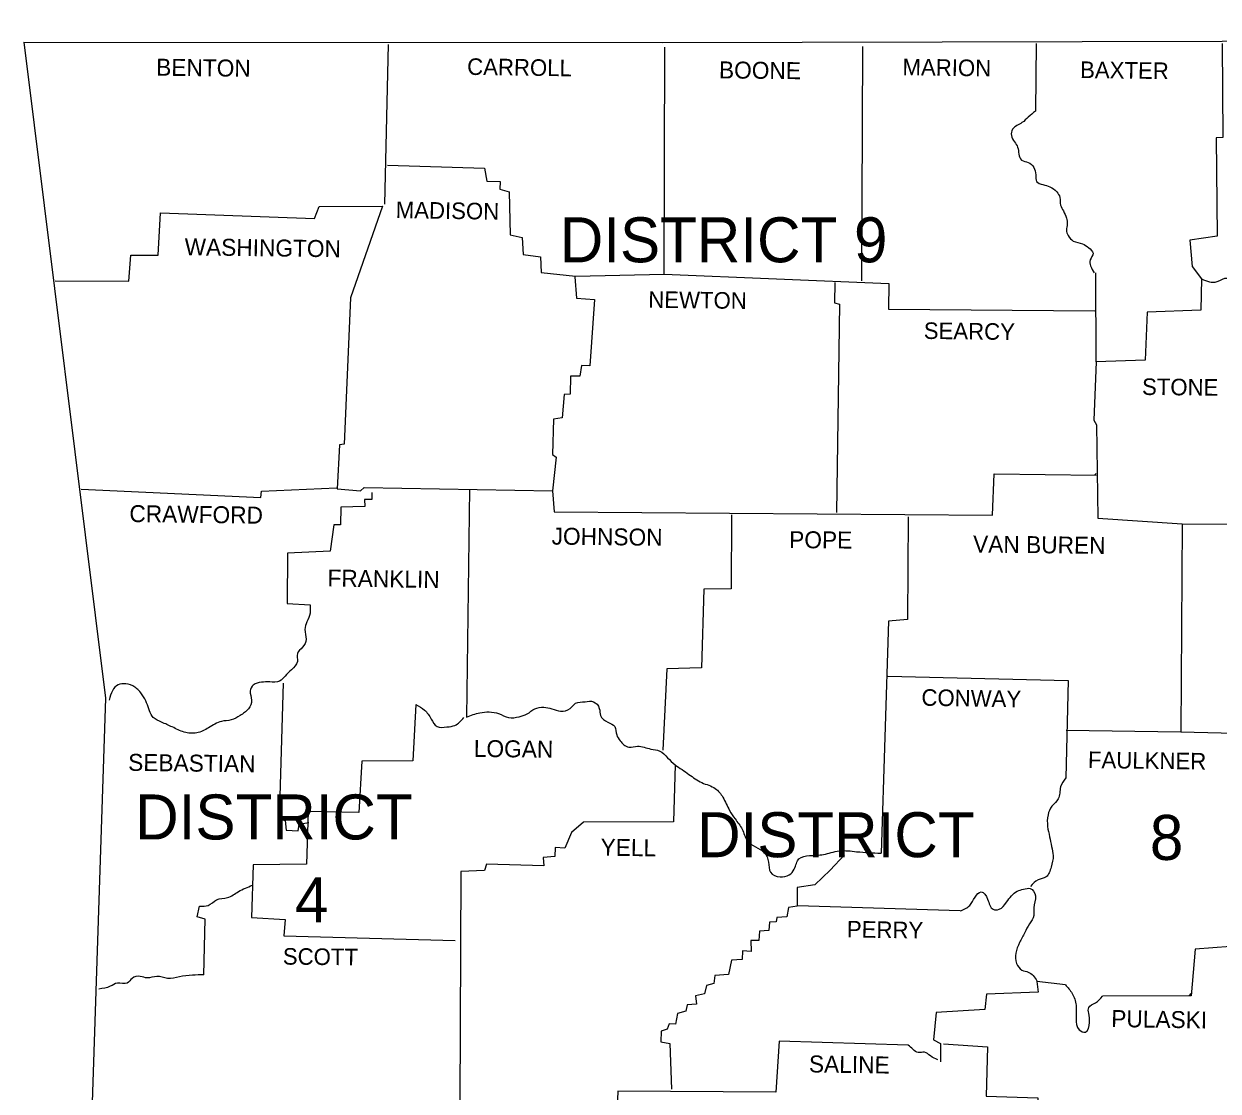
# Model space of a CAD drawing. Extents: x -42408 to 34530, y -43140 to 20491.
# Drawn here: x 1592 to 3107, y -8503 to -7149 of the extents above; entities that cross this region are included whole.
import ezdxf

# ---------------------------------------------------------------- set-up
doc = ezdxf.new("R2010")
doc.units = 0
for name, color, linetype in [('1', 7, 'Continuous'), ('2', 7, 'Continuous'), ('3', 7, 'Continuous')]:
    doc.layers.add(name, color=color, linetype=linetype)

msp = doc.modelspace()

# ---------------------------------------------------------------- linework, layer by layer
at = {"layer": '1'}
for points in [[(1592.1, -7172.4), (2401.7, -7172.9), (3112.1, -7171.4), (3950.2, -7158.4), (4338.7, -7149.4)], [(1592.1, -7172.4), (1695.7, -8004.5), (1650.7, -9362.9)], [(2054.2, -7175.4), (2049.7, -7378.2)], [(2053.2, -7328.6), (2176.4, -7332.6), (2179.4, -7348.7), (2196.4, -7349.2), (2195.9, -7359.2), (2207.9, -7362.2), (2208.9, -7416.8), (2224.4, -7420.3), (2225.4, -7441.8), (2247.5, -7444.8), (2248.5, -7464.8), (2292, -7469.3), (2404.2, -7466.8), (2405.2, -7178.9)], [(2656, -7177.9), (2654.5, -7475.3)], [(2876.3, -7174.4), (2875.3, -7260.1)], [(3112.1, -7174.4), (3113.1, -7293.6), (3104.6, -7294.1), (3106.1, -7418.8), (3071.1, -7423.8), (3074.1, -7457.3), (3086.1, -7472.8), (3085.1, -7512.4), (3017, -7514.9), (3014.5, -7576), (2952.4, -7578), (2949.4, -7652.1), (2952.9, -7658.1), (2954.4, -7776.2), (3061.5, -7783.3), (3060, -8047.1), (3145.2, -8049.6), (3145.2, -8318), (3078.1, -8323), (3073.1, -8382), (2960.4, -8382.6)], [(1631.6, -7475.3), (1725.3, -7475.8), (1727.8, -7442.8), (1762.3, -7442.8), (1765.3, -7389.2), (1960.6, -7396.2), (1966.6, -7381.2), (2047.2, -7380.7), (2006.6, -7496.9), (1998.6, -7682.6), (1992.6, -7683.1), (1989.6, -7739.2), (2019.1, -7741.7), (2023.7, -7737.2), (2262.5, -7741.7), (2265, -7768.2)], [(2404.2, -7466.8), (2689.5, -7478.8), (2689, -7511.4), (2950.9, -7513.4)], [(2952.4, -7578), (2951.9, -7465.3)], [(2291, -7470.3), (2293, -7497.4), (2316, -7498.9), (2310, -7583), (2299.5, -7582.5), (2297.5, -7596), (2285.5, -7596), (2285, -7619), (2277.5, -7619.5), (2275, -7649.1), (2264, -7650.6), (2262.5, -7695.6), (2267.5, -7699.1), (2262.5, -7741.7)], [(2621, -7477.3), (2620.5, -7503.4), (2627, -7504.9), (2623, -7769.2)], [(2265, -7768.2), (2820.7, -7772.7), (2823.2, -7720.2), (2952.4, -7721.7)], [(2950.9, -7721.2), (2952.4, -7719.7)], [(1664.7, -7739.7), (1892.5, -7750.2), (1893.5, -7742.2), (1988.6, -7737.7)], [(2157.3, -7739.7), (2153.8, -8028.6)], [(2033.7, -7743.7), (2033.7, -7752.7), (2024.2, -7752.7), (2024.7, -7761.7), (1994.1, -7762.2), (1993.6, -7784.8), (1985.1, -7784.8), (1980.6, -7818.3), (1926.5, -7820.8), (1926, -7884.4), (1955.1, -7886.4)], [(2489.8, -7772.2), (2489.3, -7865.9), (2454.7, -7866.4), (2451.7, -7966), (2407.7, -7967.5), (2402.7, -8070.6)], [(2714.1, -7774.7), (2713.1, -7904.9), (2689, -7906.9), (2679.5, -8201.3)], [(3061.5, -7783.3), (3318.9, -7784.8), (3340.9, -7774.2), (3339.4, -7970), (3324.4, -7976.5), (3310.9, -7988), (3306.4, -7992.5), (3305.9, -8048.6), (3142.1, -8048.6)], [(2688, -7976.5), (2916.8, -7982), (2913.8, -8105.7)], [(1921, -7985.5), (1916, -8157.8), (1923.5, -8159.8), (1925, -8171.8), (1940, -8172.8), (1941.5, -8164.3), (1953.6, -8162.3)], [(2089.2, -8012.6), (2085.7, -8084.2), (2020.7, -8084.7), (2017.1, -8149.7), (1952.6, -8148.2), (1950.6, -8215.3), (1883, -8215.8), (1881, -8282.9), (1923.5, -8285.4), (1922, -8305.9), (2139.3, -8312)], [(2914.3, -8045.1), (3060, -8047.1)], [(2418.2, -8089.2), (2416.2, -8161.3), (2302, -8161.8), (2287, -8174.8), (2278.5, -8194.8), (2266, -8193.8), (2265.5, -8205.3), (2251, -8206.8), (2251.5, -8217.3), (2178.9, -8215.3), (2176.4, -8223.3), (2146.3, -8224.3), (2145.3, -8517.2)], [(2633, -8203.3), (2614.9, -8222.8), (2595.4, -8241.4), (2572.9, -8244.9), (2572.9, -8268.4), (2561.9, -8269.9), (2559.9, -8281.9), (2547.4, -8282.9), (2546.4, -8288.4), (2537.8, -8288.9), (2537.3, -8299.4), (2525.3, -8299.9), (2524.3, -8312), (2514.3, -8312), (2514.8, -8326), (2503.8, -8325), (2503.3, -8336), (2489.8, -8337), (2485.8, -8355), (2468.7, -8356.5), (2467.2, -8366.5), (2458.2, -8369), (2455.7, -8379.5), (2444.2, -8382), (2445.2, -8392.6), (2433.7, -8393.6), (2431.7, -8401.6), (2421.2, -8404.6), (2418.7, -8418.1), (2410.7, -8417.6), (2408.2, -8424.6), (2400.7, -8427.1), (2400.2, -8440.6), (2411.7, -8442.6), (2413.7, -8500.7)], [(1820.4, -8355.5), (1821.9, -8284.9), (1811.9, -8281.9), (1814.9, -8268.4)], [(2779.7, -8274.4), (2573.4, -8267.9)], [(2913.3, -8368), (2877.3, -8364), (2878.8, -8377.5), (2813.2, -8380), (2811.2, -8399.6), (2749.6, -8403.1), (2746.1, -8438.1), (2755.1, -8442.6), (2755.1, -8465.7)], [(3070.6, -8381.5), (3073.1, -8379)], [(2714.1, -8444.6), (2550.4, -8439.6), (2545.9, -8504.2), (2345.6, -8503.2), (2344.6, -8524.7)], [(2758.6, -8443.1), (2814.7, -8446.6), (2812.7, -8509.2), (2878.3, -8511.7), (2879.3, -8566.3), (2910.3, -8568.8), (2910.3, -8578.3), (2939.4, -8580.3), (2940.4, -8615.4), (3006.5, -8615.4), (3008.5, -8649.9), (3069.6, -8652.9), (3069, -8718)]]:
    msp.add_lwpolyline(points, dxfattribs=at)
for points in [[(2875.3, -7260.1), (2866.3, -7267.6), (2858.3, -7274.6), (2846.3, -7283.1), (2844.8, -7291.1), (2848.8, -7299.1), (2852.8, -7305.6), (2854.3, -7314.6), (2857.8, -7322.1), (2866.3, -7325.1), (2873.3, -7331.6), (2875.8, -7340.7), (2876.8, -7349.2), (2884.8, -7353.2), (2893.8, -7356.2), (2902.3, -7362.2), (2906.3, -7369.7), (2907.3, -7379.2), (2910.8, -7386.7), (2914.8, -7395.7), (2915.8, -7403.2), (2914.8, -7410.8), (2916.8, -7417.8), (2923.4, -7424.8), (2934.9, -7428.3), (2942.9, -7433.3), (2948.4, -7440.3), (2944.9, -7448.8), (2945.4, -7456.3), (2949.9, -7465.3)], [(3086.1, -7472.8), (3106.1, -7476.3), (3118.1, -7471.8), (3126.6, -7484.9), (3131.1, -7494.9), (3138.6, -7509.4), (3150.7, -7513.9), (3159.7, -7521.9), (3159.7, -7530.4), (3151.7, -7538.4), (3145.7, -7546.4), (3147.7, -7555.9), (3149.7, -7569), (3149.7, -7581.5), (3146.7, -7593), (3144.2, -7603.5), (3146.7, -7612.5), (3156.2, -7611), (3166.2, -7603.5), (3176.7, -7603.5), (3186.7, -7609), (3197.2, -7618.5), (3207.7, -7616.5), (3216.2, -7614), (3228.3, -7610.5), (3236.8, -7615), (3244.3, -7621), (3253.3, -7630.5), (3261.8, -7636.6), (3272.8, -7642.1), (3286.3, -7645.6), (3298.9, -7654.1), (3300.9, -7668.6), (3300.4, -7681.1), (3299.4, -7696.6), (3298.4, -7713.7), (3299.9, -7730.2), (3305.4, -7741.2), (3312.4, -7754.2), (3314.4, -7766.2), (3313.9, -7785.3)], [(1955.1, -7886.4), (1955.1, -7896.9), (1951.1, -7907.9), (1948.6, -7917.4), (1950.1, -7929.9), (1945.6, -7940), (1939, -7948), (1939, -7958), (1931.5, -7968.5), (1923.5, -7976.5), (1916.5, -7983), (1904, -7984), (1893.5, -7984.5), (1883, -7988), (1879, -7995.5), (1881, -8007), (1877, -8018.1), (1866.4, -8026.6), (1854.9, -8032.1), (1842.9, -8034.1), (1826.4, -8042.1), (1811.4, -8048.6), (1795.4, -8047.6), (1780.3, -8041.1), (1766.8, -8035.1), (1756.3, -8029.1), (1747.8, -8010.6), (1742.3, -8000.5), (1732.8, -7990.5), (1721.3, -7986.5), (1711.7, -7987.5), (1700.2, -8007)], [(2089.2, -8012.6), (2100.3, -8019.6), (2108.8, -8031.1), (2116.3, -8040.6), (2128.8, -8041.1), (2138.8, -8039.1), (2150.3, -8029.1)], [(2153.8, -8028.6), (2170.4, -8023.1), (2182.4, -8022.1), (2194.4, -8024.1), (2206.9, -8029.1), (2220.4, -8028.1), (2230.4, -8024.6), (2240.4, -8018.1), (2251.5, -8016.1), (2262, -8018.1), (2273, -8021.1), (2285, -8017.6), (2292, -8011.1), (2304, -8009.1), (2314.5, -8009.1), (2322.1, -8017.6), (2323.6, -8026.6), (2333.1, -8035.1), (2341.6, -8040.6), (2344.1, -8051.1), (2348.6, -8058.6), (2353.1, -8063.6), (2359.6, -8066.6), (2370.6, -8065.6), (2387.6, -8069.1), (2398.7, -8071.6), (2408.7, -8080.1), (2418.2, -8089.2)], [(2418.2, -8089.2), (2435.7, -8101.2), (2452.2, -8111.7), (2469.2, -8119.2), (2478.8, -8130.2), (2487.3, -8147.2), (2494.3, -8157.8), (2503.3, -8170.8), (2509.8, -8185.3), (2520.3, -8193.3), (2531.3, -8200.3), (2536.8, -8212.8), (2539.3, -8225.3), (2551.4, -8231.3), (2562.9, -8228.8), (2569.4, -8221.3), (2575.4, -8208.3), (2588.9, -8204.3), (2606.4, -8202.8), (2626.5, -8198.3), (2648.5, -8199.3), (2679.5, -8201.3)], [(2913.8, -8105.7), (2907.3, -8117.2), (2904.3, -8132.2), (2896.3, -8141.7), (2891.3, -8152.7), (2890.8, -8167.3), (2893.3, -8180.3), (2895.8, -8192.8), (2897.8, -8204.3), (2895.3, -8218.8), (2888.8, -8231.3), (2878.8, -8234.9), (2869.3, -8243.4)], [(1814.9, -8268.4), (1825.9, -8267.4), (1836.4, -8260.4), (1850.4, -8257.4), (1864.4, -8249.9), (1882, -8241.9)], [(2779.7, -8274.4), (2792.2, -8267.4), (2798.7, -8256.9), (2806.7, -8250.4), (2814.7, -8259.4), (2821.7, -8272.4), (2829.2, -8272.4), (2838.7, -8263.4), (2844.8, -8255.4), (2852.3, -8249.4), (2860.3, -8246.9), (2868.8, -8245.9), (2875.3, -8255.4), (2873.3, -8270.4), (2873.3, -8280.4), (2867.8, -8290.9), (2861.8, -8301.9), (2855.3, -8314.5), (2850.3, -8328), (2851.3, -8341), (2858.3, -8349.5), (2866.3, -8352), (2877.3, -8363)], [(1820.4, -8355.5), (1805.9, -8356), (1789.3, -8358), (1774.3, -8360), (1760.8, -8357.5), (1748.3, -8359.5), (1739.8, -8357.5), (1729.3, -8360), (1723.3, -8366), (1710.7, -8366), (1701.7, -8370), (1687.2, -8373.5)], [(2913.3, -8368), (2921.9, -8379), (2926.9, -8394.1), (2926.9, -8411.1), (2930.9, -8425.1), (2938.9, -8428.1), (2943.9, -8416.1), (2942.9, -8404.1), (2942.9, -8397.1), (2951.4, -8391.1), (2960.4, -8382.6)], [(2751.6, -8463.2), (2742.1, -8458.2), (2734.6, -8453.6), (2726.6, -8454.1), (2720.1, -8450.1), (2714.1, -8444.6)]]:
    msp.add_spline(points, degree=3, dxfattribs=at)

# ---------------------------------------------------------------- texts
at = {"layer": '2'}
for s, height, rotation, p in [('BENTON', 21.53, 359.2527, (1759.8, -7215)), ('CARROLL', 21.03, 359.1481, (2154.3, -7214)), ('MARION', 21.03, 359.1854, (2706.6, -7214.5)), ('BOONE', 21.53, 359.4001, (2473.8, -7218.5)), ('BAXTER', 21.03, 359.2559, (2931.9, -7218)), ('MADISON', 21.03, 359.0906, (2063.7, -7395.7)), ('WASHINGTON', 21.52, 359.232, (1795.9, -7442.8)), ('NEWTON', 21.03, 359.2717, (2384.1, -7509.4)), ('SEARCY', 21.02, 359.2527, (2733.6, -7548.9)), ('STONE', 21.02, 359.4001, (3010.5, -7620)), ('CRAWFORD', 21.52, 359.2771, (1725.8, -7781.2)), ('JOHNSON', 21.53, 359.3514, (2261.5, -7809.8)), ('POPE', 21.53, 359.6155, (2562.9, -7814.3)), ('VAN BUREN', 21.53, 359.3508, (2796.2, -7819.8)), ('FRANKLIN', 21.53, 359.1815, (1977.1, -7862.9)), ('CONWAY', 21.02, 359.0371, (2730.6, -8014.1)), ('LOGAN', 21.53, 359.3969, (2162.8, -8079.1)), ('SEBASTIAN', 21.52, 359.2816, (1724.3, -8096.7)), ('FAULKNER', 21.03, 359.2486, (2941.9, -8093.2)), ('YELL', 21.53, 359.1987, (2323.6, -8204.3)), ('PERRY', 21.03, 359.0858, (2636, -8308)), ('SCOTT', 21.03, 359.4063, (1920.5, -8342.5)), ('PULASKI', 21.53, 359.053, (2971.4, -8421.6)), ('SALINE', 21.53, 359.1491, (2587.9, -8479.2))]:
    msp.add_text(s, height=height, rotation=rotation, dxfattribs=at).set_placement(p)
at = {"layer": '3'}
for s, height, p in [('DISTRICT 9', 57.08, (2272, -7451.8)), ('DISTRICT', 57.08, (1733.3, -8183.8)), ('DISTRICT', 57.08, (2446.2, -8206.3)), ('8', 57.1, (3020.5, -8209.8)), ('4', 57.1, (1936, -8288.9))]:
    msp.add_text(s, height=height, dxfattribs=at).set_placement(p)

doc.saveas('drawing.dxf')
